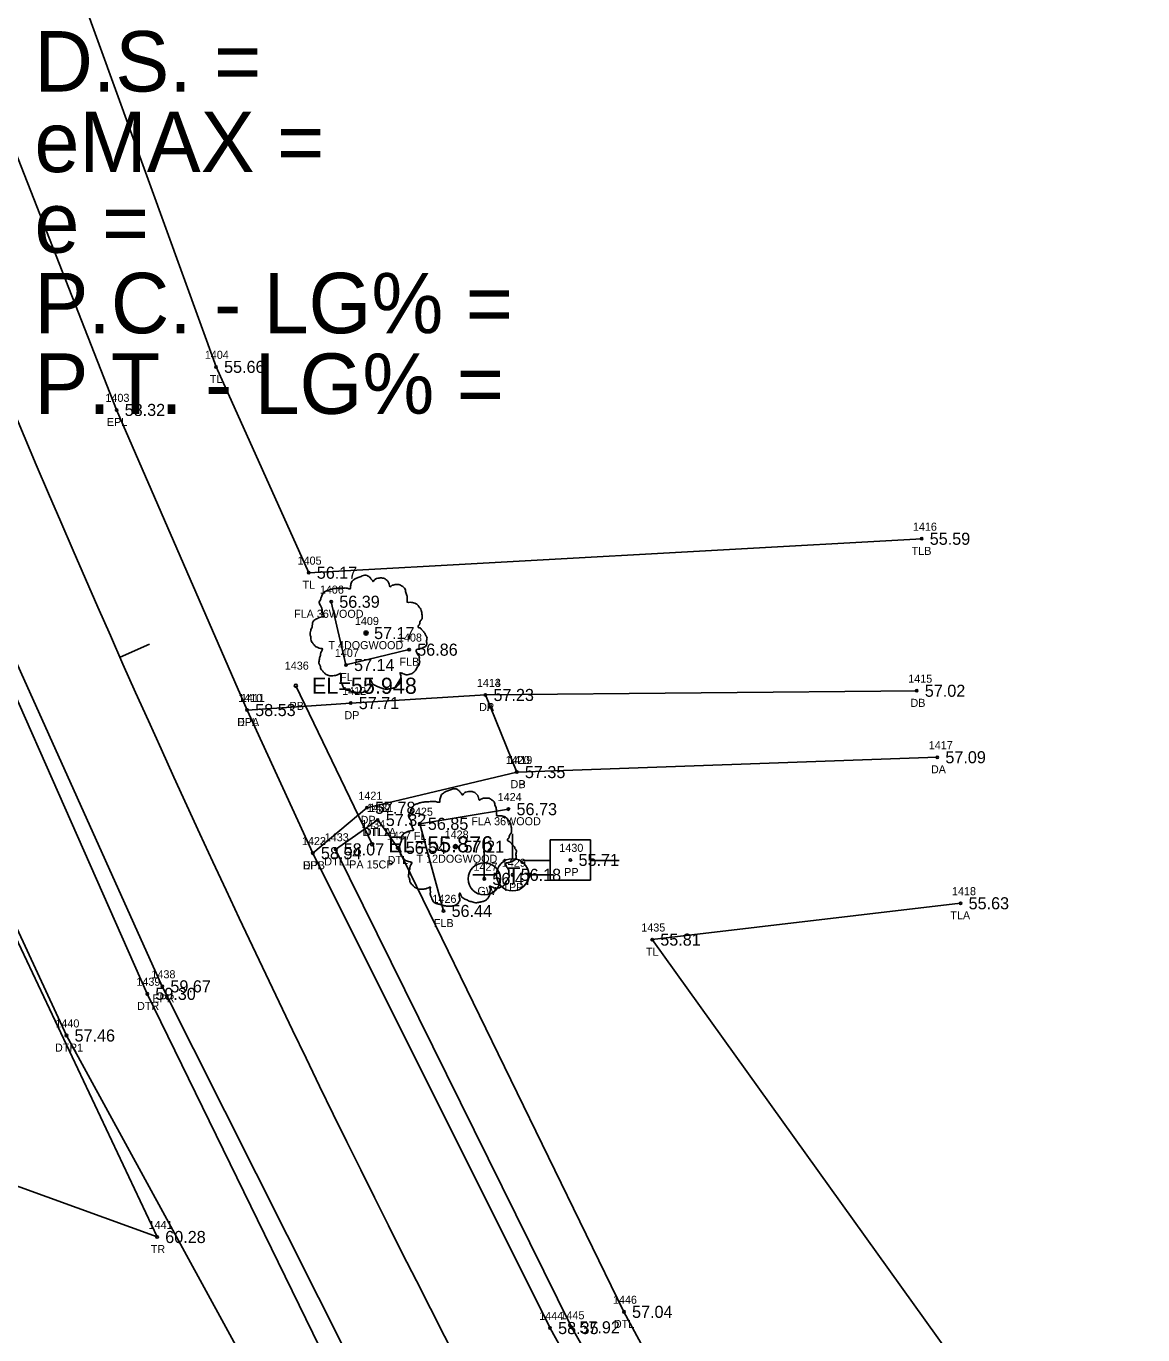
# Model space of a CAD drawing. Extents: x 2396531 to 2397633, y 770203 to 772837.
# Drawn here: x 2397143 to 2397281.5, y 771003.7 to 771166.1 of the extents above; entities that cross this region are included whole.
import ezdxf

# ---------------------------------------------------------------- set-up
doc = ezdxf.new("R2010")
doc.units = 0
for name, color, linetype in [('RD_EX_DR_Pipe', 7, 'Continuous'), ('RD_EX_DR_Pipe_txCode', 7, 'Continuous'), ('RD_EX_Driveway', 7, 'Continuous'), ('RD_EX_Driveway_txCode', 7, 'Continuous'), ('RD_EX_Fence_Other', 7, 'Continuous'), ('RD_EX_Fence_Other_txCode', 7, 'Continuous'), ('RD_EX_H2O', 7, 'Continuous'), ('RD_EX_H2O_txCode', 7, 'Continuous'), ('RD_EX_Road', 7, 'Continuous'), ('RD_EX_Road_txCode', 7, 'Continuous'), ('RD_EX_TX_Driveway_ELEV', 7, 'Continuous'), ('RD_EX_TX_Fence_Other_ELEV', 7, 'Continuous'), ('RD_EX_TX_H2O_ELEV', 7, 'Continuous'), ('RD_EX_TX_Road_ELEV', 7, 'Continuous'), ('RD_EX_TX_UT_ELEV', 7, 'Continuous'), ('RD_EX_TX_VEG_ELEV', 7, 'Continuous'), ('RD_EX_UT', 7, 'Continuous'), ('RD_EX_UT_txCode', 7, 'Continuous'), ('RD_EX_VEG', 7, 'Continuous'), ('RD_EX_VEG_txCode', 7, 'Continuous'), ('RD_HC_Cl', 7, 'Continuous'), ('RD_HC_Data', 7, 'Continuous'), ('RD_HC_Data_Tic', 7, 'Continuous'), ('RD_HC_Survey_ELEV', 7, 'Continuous'), ('RD_SMD_Locator', 7, 'Continuous'), ('RD_TX_Pipe_ElevEX', 7, 'Continuous')]:
    doc.layers.add(name, color=color, linetype=linetype)

msp = doc.modelspace()

# ---------------------------------------------------------------- linework, layer by layer
at = {"layer": 'RD_EX_DR_Pipe'}
msp.add_line((2397185.88, 771064.59), (2397176.42, 771084.26), dxfattribs=at)
at = {"layer": 'RD_EX_Driveway'}
for p, q in [((2397199.94, 771083.12), (2397253.45, 771083.64)), ((2397256, 771075.39), (2397203.84, 771073.55))]:
    msp.add_line(p, q, dxfattribs=at)
msp.add_lwpolyline([(2397170.38, 771081.25), (2397183.23, 771082.11), (2397199.94, 771083.12), (2397203.84, 771073.55), (2397185.24, 771069.12), (2397178.53, 771063.49)], dxfattribs=at)
at = {"layer": 'RD_EX_Fence_Other'}
for points in [[(2397180.81, 771094.69), (2397182.64, 771086.84), (2397190.48, 771088.74)], [(2397202.8, 771068.95), (2397191.8, 771067.13), (2397194.74, 771056.32)]]:
    msp.add_lwpolyline(points, dxfattribs=at)
at = {"layer": 'RD_EX_H2O'}
for points in [[(2397108.85, 771101.86), (2397130.27, 771108.67), (2397157.99, 771046.03), (2397184.53, 770991.63), (2397224.53, 770918.86), (2397257.48, 770863.23)], [(2397108.85, 771101.86), (2397123.52, 771093.58), (2397147.97, 771040.86), (2397177.5, 770986.79), (2397217.86, 770915.5), (2397251.15, 770859.33)], [(2397186.58, 771067.61), (2397181.36, 771063.96), (2397210.6, 771004.65), (2397241.1, 770951.7), (2397245.58, 770954.05)], [(2397186.58, 771067.61), (2397189.06, 771064.15), (2397217.13, 771006.57), (2397245.58, 770954.05)]]:
    msp.add_lwpolyline(points, dxfattribs=at)
at = {"layer": 'RD_EX_Road'}
for points in [[(2397113.76, 771228.75), (2397130.87, 771177.98), (2397154.19, 771118.49), (2397170.38, 771081.25), (2397178.53, 771063.49), (2397207.96, 771004.56), (2397238.54, 770949.11), (2397245.72, 770936.59), (2397280.76, 770876.73)], [(2397093.16, 771212.62), (2397108.35, 771171.65), (2397122.66, 771133.29), (2397131.66, 771109.5), (2397159.86, 771046.96), (2397187.02, 770992.86), (2397227.29, 770920.43), (2397260.16, 770864.73)]]:
    msp.add_lwpolyline(points, dxfattribs=at)
at = {"layer": 'RD_EX_UT'}
for p, q in [((2397199.8, 771060.3), (2397199.8, 771065.3)), ((2397203.31, 771065.87), (2397203.31, 771062.8)), ((2397212.98, 771065.15), (2397207.98, 771065.15)), ((2397207.98, 771065.15), (2397207.98, 771060.15)), ((2397212.98, 771060.15), (2397212.98, 771065.15)), ((2397204.55, 771062.59), (2397208.02, 771062.59)), ((2397212.91, 771062.59), (2397216.55, 771062.59)), ((2397198.38, 771060.81), (2397201.31, 771060.81)), ((2397205.31, 771060.81), (2397208.38, 771060.81)), ((2397207.98, 771060.15), (2397212.98, 771060.15))]:
    msp.add_line(p, q, dxfattribs=at)
for centre in [(2397199.8, 771060.3), (2397203.31, 771060.8)]:
    msp.add_circle(centre, 2, dxfattribs=at)
at = {"layer": 'RD_EX_VEG'}
for points in [[(2397137.17, 771710.16), (2397010.6, 771680.28), (2397078.29, 771429.37), (2397127.02, 771232.69), (2397127.02, 771232.69), (2397166.52, 771123.83), (2397178.02, 771098.29), (2397254.06, 771102.5)], [(2397070.27, 771071.96), (2397126.14, 771085.88), (2397159.22, 771015.86), (2397135.58, 771024.43), (2397104.64, 771007.32)], [(2397258.88, 771057.27), (2397220.63, 771052.76), (2397280.9, 770968.68), (2397351.86, 770905.86)]]:
    msp.add_lwpolyline(points, dxfattribs=at)
for centre, radius in [((2397185.13, 771090.8), 0.25), ((2397185.12, 771090.78), 0.0001), ((2397196.23, 771064.3), 0.25), ((2397196.22, 771064.28), 0.0001)]:
    msp.add_circle(centre, radius, dxfattribs=at)
for points in [[(2397185.26, 771097.96), (2397184.97, 771097.99), (2397184.64, 771097.89), (2397184.39, 771097.79), (2397184.17, 771097.71), (2397183.94, 771097.61), (2397183.64, 771097.44), (2397183.42, 771097.24), (2397183.29, 771096.99), (2397183.24, 771096.76), (2397183.19, 771096.49), (2397183.19, 771096.31), (2397183.07, 771096.29), (2397182.92, 771096.31), (2397182.67, 771096.39), (2397182.42, 771096.39), (2397182.17, 771096.39), (2397181.82, 771096.36), (2397181.47, 771096.36), (2397181.19, 771096.31), (2397180.87, 771096.26), (2397180.49, 771096.14), (2397180.14, 771096.01), (2397179.84, 771095.76), (2397179.59, 771095.29), (2397179.47, 771094.94), (2397179.32, 771094.69), (2397179.47, 771094.24), (2397179.64, 771093.89), (2397179.67, 771093.69), (2397179.74, 771093.27), (2397179.84, 771093.04), (2397179.97, 771092.84), (2397179.89, 771092.82), (2397179.52, 771092.77), (2397179.22, 771092.67), (2397178.79, 771092.44), (2397178.57, 771092.22), (2397178.47, 771091.89), (2397178.44, 771091.54), (2397178.34, 771091.34), (2397178.27, 771091.07), (2397178.24, 771090.99), (2397178.19, 771090.67), (2397178.29, 771090.22), (2397178.32, 771089.87), (2397178.44, 771089.64), (2397178.59, 771089.47), (2397178.77, 771089.22), (2397179.17, 771088.99), (2397179.49, 771088.89), (2397179.69, 771088.87), (2397179.52, 771088.37), (2397179.47, 771088.02), (2397179.34, 771087.62), (2397179.34, 771087.54), (2397179.29, 771087.07), (2397179.44, 771086.74), (2397179.52, 771086.37), (2397179.69, 771086.14), (2397179.97, 771085.84), (2397180.29, 771085.62), (2397180.79, 771085.49), (2397181.19, 771085.52), (2397181.77, 771085.69), (2397182.02, 771085.77), (2397181.99, 771085.59), (2397182.02, 771085.22), (2397182.02, 771084.79), (2397182.17, 771084.47), (2397182.27, 771084.19), (2397182.42, 771083.94), (2397182.74, 771083.72), (2397183.14, 771083.64), (2397183.57, 771083.49), (2397184.02, 771083.42), (2397184.52, 771083.39), (2397185.12, 771083.54), (2397185.39, 771083.67), (2397185.49, 771083.84), (2397185.69, 771084.22), (2397185.64, 771084.44), (2397185.66, 771085.04), (2397185.76, 771084.87), (2397185.94, 771084.52), (2397186.44, 771084.22), (2397186.84, 771084.04), (2397187.31, 771083.89), (2397187.61, 771083.82), (2397188.09, 771083.89), (2397188.46, 771083.97), (2397188.84, 771084.09), (2397189.14, 771084.37), (2397189.31, 771084.64), (2397189.36, 771084.92), (2397189.44, 771085.29), (2397189.49, 771085.47)], [(2397189.49, 771085.47), (2397189.41, 771085.64), (2397189.36, 771085.89), (2397189.44, 771085.87), (2397189.61, 771085.82), (2397189.89, 771085.69), (2397190.11, 771085.62), (2397190.44, 771085.64), (2397190.71, 771085.74), (2397191.16, 771086.02), (2397191.44, 771086.49), (2397191.71, 771086.89), (2397191.79, 771087.22), (2397191.74, 771087.44), (2397191.71, 771087.94), (2397191.51, 771088.19), (2397191.46, 771088.32), (2397191.36, 771088.72), (2397191.44, 771088.77), (2397191.71, 771088.82), (2397192.09, 771088.94), (2397192.36, 771089.07), (2397192.59, 771089.24), (2397192.66, 771089.47), (2397192.64, 771089.87), (2397192.69, 771090.27), (2397192.61, 771090.42), (2397192.51, 771090.57), (2397192.44, 771090.77), (2397192.29, 771090.92), (2397192.19, 771091.07), (2397192.09, 771091.17), (2397191.96, 771091.32), (2397191.79, 771091.44), (2397191.64, 771091.49), (2397191.59, 771091.64), (2397191.74, 771091.84), (2397191.79, 771091.94), (2397191.81, 771092.17), (2397192.04, 771092.52), (2397192.09, 771092.92), (2397192.04, 771093.34), (2397191.99, 771093.62), (2397191.84, 771093.89), (2397191.64, 771094.14), (2397191.51, 771094.32), (2397191.34, 771094.44), (2397191.01, 771094.56), (2397190.76, 771094.61), (2397190.41, 771094.61), (2397190.21, 771094.66), (2397190.24, 771094.71), (2397190.24, 771094.86), (2397190.24, 771095.14), (2397190.16, 771095.59), (2397190.01, 771096.09), (2397190.01, 771096.11), (2397189.91, 771096.36), (2397189.69, 771096.56), (2397189.51, 771096.66), (2397189.31, 771096.79), (2397189.06, 771096.81), (2397188.76, 771096.81), (2397188.49, 771096.76), (2397188.29, 771096.66), (2397188.11, 771096.54), (2397188.04, 771096.69), (2397187.94, 771096.99), (2397187.89, 771097.14), (2397187.74, 771097.31), (2397187.51, 771097.51), (2397187.06, 771097.64), (2397186.44, 771097.56), (2397186.14, 771097.36), (2397185.99, 771097.19), (2397185.94, 771097.31), (2397185.74, 771097.51), (2397185.64, 771097.69), (2397185.46, 771097.81), (2397185.31, 771097.91), (2397185.21, 771097.96)], [(2397196.36, 771071.47), (2397196.06, 771071.49), (2397195.74, 771071.39), (2397195.49, 771071.29), (2397195.26, 771071.22), (2397195.04, 771071.12), (2397194.74, 771070.95), (2397194.51, 771070.75), (2397194.39, 771070.5), (2397194.34, 771070.27), (2397194.29, 771070), (2397194.29, 771069.82), (2397194.16, 771069.8), (2397194.01, 771069.82), (2397193.76, 771069.9), (2397193.51, 771069.9), (2397193.26, 771069.9), (2397192.91, 771069.87), (2397192.56, 771069.87), (2397192.29, 771069.82), (2397191.96, 771069.77), (2397191.59, 771069.65), (2397191.24, 771069.52), (2397190.94, 771069.27), (2397190.69, 771068.8), (2397190.56, 771068.45), (2397190.41, 771068.2), (2397190.56, 771067.75), (2397190.74, 771067.4), (2397190.76, 771067.2), (2397190.84, 771066.77), (2397190.94, 771066.55), (2397191.06, 771066.35), (2397190.99, 771066.32), (2397190.61, 771066.27), (2397190.31, 771066.17), (2397189.89, 771065.95), (2397189.66, 771065.72), (2397189.56, 771065.4), (2397189.54, 771065.05), (2397189.44, 771064.85), (2397189.36, 771064.57), (2397189.34, 771064.5), (2397189.29, 771064.17), (2397189.39, 771063.72), (2397189.41, 771063.37), (2397189.54, 771063.15), (2397189.69, 771062.97), (2397189.86, 771062.72), (2397190.26, 771062.5), (2397190.59, 771062.4), (2397190.79, 771062.37), (2397190.61, 771061.87), (2397190.56, 771061.52), (2397190.44, 771061.12), (2397190.44, 771061.05), (2397190.39, 771060.57), (2397190.54, 771060.25), (2397190.61, 771059.87), (2397190.79, 771059.65), (2397191.06, 771059.35), (2397191.39, 771059.13), (2397191.89, 771059), (2397192.29, 771059.03), (2397192.86, 771059.2), (2397193.11, 771059.28), (2397193.09, 771059.1), (2397193.11, 771058.73), (2397193.11, 771058.3), (2397193.26, 771057.98), (2397193.36, 771057.7), (2397193.51, 771057.45), (2397193.84, 771057.23), (2397194.24, 771057.15), (2397194.66, 771057), (2397195.11, 771056.93), (2397195.61, 771056.9), (2397196.21, 771057.05), (2397196.49, 771057.18), (2397196.59, 771057.35), (2397196.78, 771057.73), (2397196.73, 771057.95), (2397196.76, 771058.55), (2397196.86, 771058.38), (2397197.03, 771058.03), (2397197.53, 771057.73), (2397197.93, 771057.55), (2397198.41, 771057.4), (2397198.71, 771057.33), (2397199.18, 771057.4), (2397199.56, 771057.48), (2397199.93, 771057.6), (2397200.23, 771057.88), (2397200.41, 771058.15), (2397200.46, 771058.43), (2397200.53, 771058.8), (2397200.58, 771058.98)], [(2397200.58, 771058.98), (2397200.51, 771059.15), (2397200.46, 771059.4), (2397200.53, 771059.38), (2397200.71, 771059.33), (2397200.98, 771059.2), (2397201.21, 771059.13), (2397201.53, 771059.15), (2397201.81, 771059.25), (2397202.26, 771059.53), (2397202.53, 771060), (2397202.81, 771060.4), (2397202.88, 771060.72), (2397202.83, 771060.95), (2397202.81, 771061.45), (2397202.61, 771061.7), (2397202.56, 771061.82), (2397202.46, 771062.22), (2397202.53, 771062.27), (2397202.81, 771062.32), (2397203.18, 771062.45), (2397203.46, 771062.57), (2397203.68, 771062.75), (2397203.76, 771062.97), (2397203.73, 771063.37), (2397203.78, 771063.77), (2397203.71, 771063.92), (2397203.61, 771064.07), (2397203.53, 771064.27), (2397203.38, 771064.42), (2397203.28, 771064.57), (2397203.18, 771064.67), (2397203.06, 771064.82), (2397202.88, 771064.95), (2397202.73, 771065), (2397202.68, 771065.15), (2397202.83, 771065.35), (2397202.88, 771065.45), (2397202.91, 771065.67), (2397203.13, 771066.02), (2397203.18, 771066.42), (2397203.13, 771066.85), (2397203.08, 771067.12), (2397202.93, 771067.4), (2397202.73, 771067.65), (2397202.61, 771067.82), (2397202.43, 771067.95), (2397202.11, 771068.07), (2397201.86, 771068.12), (2397201.51, 771068.12), (2397201.31, 771068.17), (2397201.33, 771068.22), (2397201.33, 771068.37), (2397201.33, 771068.65), (2397201.26, 771069.1), (2397201.11, 771069.6), (2397201.11, 771069.62), (2397201.01, 771069.87), (2397200.78, 771070.07), (2397200.61, 771070.17), (2397200.41, 771070.3), (2397200.16, 771070.32), (2397199.86, 771070.32), (2397199.58, 771070.27), (2397199.38, 771070.17), (2397199.21, 771070.05), (2397199.13, 771070.2), (2397199.03, 771070.5), (2397198.98, 771070.65), (2397198.83, 771070.82), (2397198.61, 771071.02), (2397198.16, 771071.14), (2397197.53, 771071.07), (2397197.23, 771070.87), (2397197.08, 771070.7), (2397197.03, 771070.82), (2397196.83, 771071.02), (2397196.73, 771071.19), (2397196.56, 771071.32), (2397196.41, 771071.42), (2397196.31, 771071.47)]]:
    msp.add_spline(points, degree=3, dxfattribs=at)
at = {"layer": 'RD_HC_Cl'}
msp.add_arc((2398682.18, 771766.08), 1671.39, 194.59125, 211.50817, dxfattribs=at)
at = {"layer": 'RD_HC_Data_Tic'}
msp.add_line((2397154.61, 771087.8), (2397158.27, 771089.42), dxfattribs=at)
at = {"layer": 'RD_SMD_Locator'}
for centre, radius in [((2397166.52, 771123.83), 0.15), ((2397154.19, 771118.49), 0.15), ((2397254.06, 771102.5), 0.15), ((2397178.02, 771098.29), 0.15), ((2397180.81, 771094.69), 0.15), ((2397185.13, 771090.8), 0.15), ((2397190.48, 771088.74), 0.15), ((2397182.64, 771086.84), 0.15), ((2397176.42, 771084.26), 0.2), ((2397199.94, 771083.12), 0.15), ((2397199.94, 771083.12), 0.15), ((2397253.45, 771083.64), 0.15), ((2397170.38, 771081.25), 0.15), ((2397170.38, 771081.25), 0.15), ((2397183.23, 771082.11), 0.15), ((2397256, 771075.39), 0.15), ((2397203.84, 771073.55), 0.15), ((2397203.84, 771073.55), 0.15), ((2397185.24, 771069.12), 0.15), ((2397202.8, 771068.95), 0.15), ((2397186.58, 771067.61), 0.15), ((2397186.58, 771067.61), 0.15), ((2397191.8, 771067.13), 0.15), ((2397178.53, 771063.49), 0.15), ((2397178.53, 771063.49), 0.15), ((2397181.36, 771063.96), 0.15), ((2397185.88, 771064.59), 0.2), ((2397189.06, 771064.15), 0.15), ((2397196.23, 771064.3), 0.15), ((2397210.49, 771062.65), 0.15), ((2397199.8, 771060.3), 0.15), ((2397203.31, 771060.8), 0.15), ((2397258.88, 771057.27), 0.15), ((2397194.74, 771056.32), 0.15), ((2397220.63, 771052.76), 0.15), ((2397157.99, 771046.03), 0.15), ((2397159.86, 771046.96), 0.15), ((2397147.97, 771040.86), 0.15), ((2397159.22, 771015.86), 0.15), ((2397217.13, 771006.57), 0.15), ((2397207.96, 771004.56), 0.15), ((2397210.6, 771004.65), 0.15)]:
    msp.add_circle(centre, radius, dxfattribs=at)

# ---------------------------------------------------------------- texts
at = {"layer": 'RD_EX_DR_Pipe_txCode'}
for s, p in [('1436', (2397175.05, 771086.26)), ('PB', (2397175.64, 771081.26)), ('1434', (2397184.53, 771066.59)), ('PA 15CP', (2397183.04, 771061.59))]:
    msp.add_text(s, height=1, dxfattribs=at).set_placement(p)
at = {"layer": 'RD_EX_Driveway_txCode'}
for s, p in [('1413', (2397198.88, 771084.12)), ('1414', (2397198.88, 771084.12)), ('1415', (2397252.39, 771084.64)), ('1411', (2397169.6, 771082.25)), ('1412', (2397182.17, 771083.11)), ('DA', (2397199.15, 771081.12)), ('DP', (2397199.16, 771081.12)), ('DB', (2397252.67, 771081.64)), ('DPA', (2397169.12, 771079.25)), ('DP', (2397182.45, 771080.11)), ('1417', (2397254.94, 771076.39)), ('1420', (2397202.46, 771074.55)), ('1419', (2397202.78, 771074.55)), ('DA', (2397255.21, 771073.39)), ('DB', (2397203.06, 771071.55)), ('DP', (2397203.06, 771071.55)), ('1421', (2397184.18, 771070.12)), ('DP', (2397184.46, 771067.12)), ('1422', (2397177.18, 771064.49)), ('DPB', (2397177.28, 771061.49))]:
    msp.add_text(s, height=1, dxfattribs=at).set_placement(p)
at = {"layer": 'RD_EX_Fence_Other_txCode'}
for s, p in [('1406', (2397179.4, 771095.69)), ('FLA 36WOOD', (2397176.2, 771092.69)), ('1408', (2397189.09, 771089.74)), ('1407', (2397181.26, 771087.84)), ('FLB', (2397189.27, 771086.74)), ('FL', (2397181.91, 771084.84)), ('1424', (2397201.46, 771069.95)), ('1425', (2397190.45, 771068.13)), ('FLA 36WOOD', (2397198.19, 771066.95)), ('FL', (2397191.07, 771065.13)), ('1426', (2397193.37, 771057.32)), ('FLB', (2397193.54, 771054.32))]:
    msp.add_text(s, height=1, dxfattribs=at).set_placement(p)
at = {"layer": 'RD_EX_H2O_txCode'}
for s, p in [('1432', (2397185.24, 771068.61)), ('1431', (2397185.52, 771068.61)), ('1433', (2397180.01, 771064.96)), ('DTL1A', (2397184.69, 771065.61)), ('DTLA', (2397184.85, 771065.61)), ('1437', (2397187.71, 771065.15)), ('DTL1', (2397179.95, 771061.96)), ('DTL', (2397187.81, 771062.15)), ('1439', (2397156.64, 771047.03)), ('DTR', (2397156.72, 771044.03)), ('1440', (2397146.59, 771041.86)), ('DTR1', (2397146.54, 771038.86)), ('1446', (2397215.76, 771007.57)), ('1445', (2397209.25, 771005.65)), ('DTL', (2397215.88, 771004.57))]:
    msp.add_text(s, height=1, dxfattribs=at).set_placement(p)
at = {"layer": 'RD_EX_Road_txCode'}
for s, p in [('1403', (2397152.8, 771119.49)), ('EPL', (2397152.98, 771116.49)), ('1410', (2397169.28, 771082.25)), ('EPL', (2397169.18, 771079.25)), ('1423', (2397177.18, 771064.49)), ('EPL', (2397177.32, 771061.49)), ('1438', (2397158.51, 771047.96)), ('EPR', (2397158.63, 771044.96)), ('1444', (2397206.61, 771005.56))]:
    msp.add_text(s, height=1, dxfattribs=at).set_placement(p)
at = {"layer": 'RD_EX_TX_Driveway_ELEV'}
for s, p in [('57.23', (2397200.94, 771082.37)), ('57.23', (2397200.94, 771082.37)), ('57.02', (2397254.45, 771082.89)), ('58.53', (2397171.38, 771080.5)), ('57.71', (2397184.23, 771081.36)), ('57.09', (2397257, 771074.64)), ('57.35', (2397204.84, 771072.8)), ('57.35', (2397204.84, 771072.8)), ('57.78', (2397186.24, 771068.37)), ('58.54', (2397179.53, 771062.74))]:
    msp.add_text(s, height=1.5, dxfattribs=at).set_placement(p)
at = {"layer": 'RD_EX_TX_Fence_Other_ELEV'}
for s, p in [('56.39', (2397181.81, 771093.94)), ('56.86', (2397191.48, 771087.99)), ('57.14', (2397183.64, 771086.09)), ('56.73', (2397203.8, 771068.2)), ('56.85', (2397192.8, 771066.38)), ('56.44', (2397195.74, 771055.57))]:
    msp.add_text(s, height=1.5, dxfattribs=at).set_placement(p)
at = {"layer": 'RD_EX_TX_H2O_ELEV'}
for s, p in [('57.32', (2397187.58, 771066.86)), ('57.32', (2397187.58, 771066.86)), ('58.07', (2397182.36, 771063.21)), ('56.54', (2397190.06, 771063.4)), ('59.30', (2397158.99, 771045.28)), ('57.46', (2397148.97, 771040.11)), ('57.04', (2397218.13, 771005.82)), ('57.92', (2397211.6, 771003.9))]:
    msp.add_text(s, height=1.5, dxfattribs=at).set_placement(p)
at = {"layer": 'RD_EX_TX_Road_ELEV'}
for s, p in [('58.32', (2397155.19, 771117.74)), ('58.53', (2397171.38, 771080.5)), ('58.54', (2397179.53, 771062.74)), ('59.67', (2397160.86, 771046.21)), ('58.35', (2397208.96, 771003.81))]:
    msp.add_text(s, height=1.5, dxfattribs=at).set_placement(p)
at = {"layer": 'RD_EX_TX_UT_ELEV'}
for s, p in [('56.47', (2397200.8, 771059.55)), ('56.18', (2397204.31, 771060.05))]:
    msp.add_text(s, height=1.5, dxfattribs=at).set_placement(p)
at = {"layer": 'RD_EX_TX_VEG_ELEV'}
for s, p in [('55.66', (2397167.52, 771123.08)), ('55.59', (2397255.06, 771101.75)), ('56.17', (2397179.02, 771097.54)), ('57.17', (2397186.13, 771090.05)), ('57.21', (2397197.23, 771063.55)), ('55.63', (2397259.88, 771056.52)), ('55.81', (2397221.63, 771052.01)), ('60.28', (2397160.22, 771015.11))]:
    msp.add_text(s, height=1.5, dxfattribs=at).set_placement(p)
at = {"layer": 'RD_EX_UT'}
msp.add_text('T', height=2, dxfattribs=at).set_placement((2397202.64, 771059.75))
at = {"layer": 'RD_EX_UT_txCode'}
for s, p in [('1430', (2397209.11, 771063.65)), ('1427', (2397198.46, 771061.3)), ('1429', (2397201.97, 771061.8)), ('PP', (2397209.71, 771060.65)), ('GW', (2397198.96, 771058.3)), ('TPP', (2397202.05, 771058.8))]:
    msp.add_text(s, height=1, dxfattribs=at).set_placement(p)
at = {"layer": 'RD_EX_VEG_txCode'}
for s, p in [('1404', (2397165.13, 771124.83)), ('TL', (2397165.75, 771121.83)), ('1416', (2397252.97, 771103.5)), ('TLB', (2397252.82, 771100.5)), ('1405', (2397176.64, 771099.29)), ('TL', (2397177.25, 771096.29)), ('1409', (2397183.75, 771091.8)), ('T 4DOGWOOD', (2397180.46, 771088.8)), ('1428', (2397194.88, 771065.3)), ('T 12DOGWOOD', (2397191.39, 771062.3)), ('1418', (2397257.82, 771058.27)), ('TLA', (2397257.62, 771055.27)), ('1435', (2397219.28, 771053.76)), ('TL', (2397219.86, 771050.76)), ('1441', (2397158.15, 771016.86)), ('TR', (2397158.42, 771013.86))]:
    msp.add_text(s, height=1, dxfattribs=at).set_placement(p)
at = {"layer": 'RD_HC_Data'}
for s, p in [('D.S. = ', (2397144, 771158)), ('eMAX = ', (2397144, 771148)), ('e = ', (2397144, 771138)), ('P.C. - LG% = ', (2397144, 771128)), ('P.T. - LG% = ', (2397144, 771118))]:
    msp.add_text(s, height=7.5, dxfattribs=at).set_placement(p)
at = {"layer": 'RD_HC_Survey_ELEV'}
msp.add_text('55.71', height=1.5, dxfattribs=at).set_placement((2397211.49, 771061.9))
at = {"layer": 'RD_TX_Pipe_ElevEX'}
for s, p in [('EL=55.948', (2397178.42, 771083.26)), ('EL=55.876', (2397187.88, 771063.59))]:
    msp.add_text(s, height=2, dxfattribs=at).set_placement(p)

doc.saveas('drawing.dxf')
